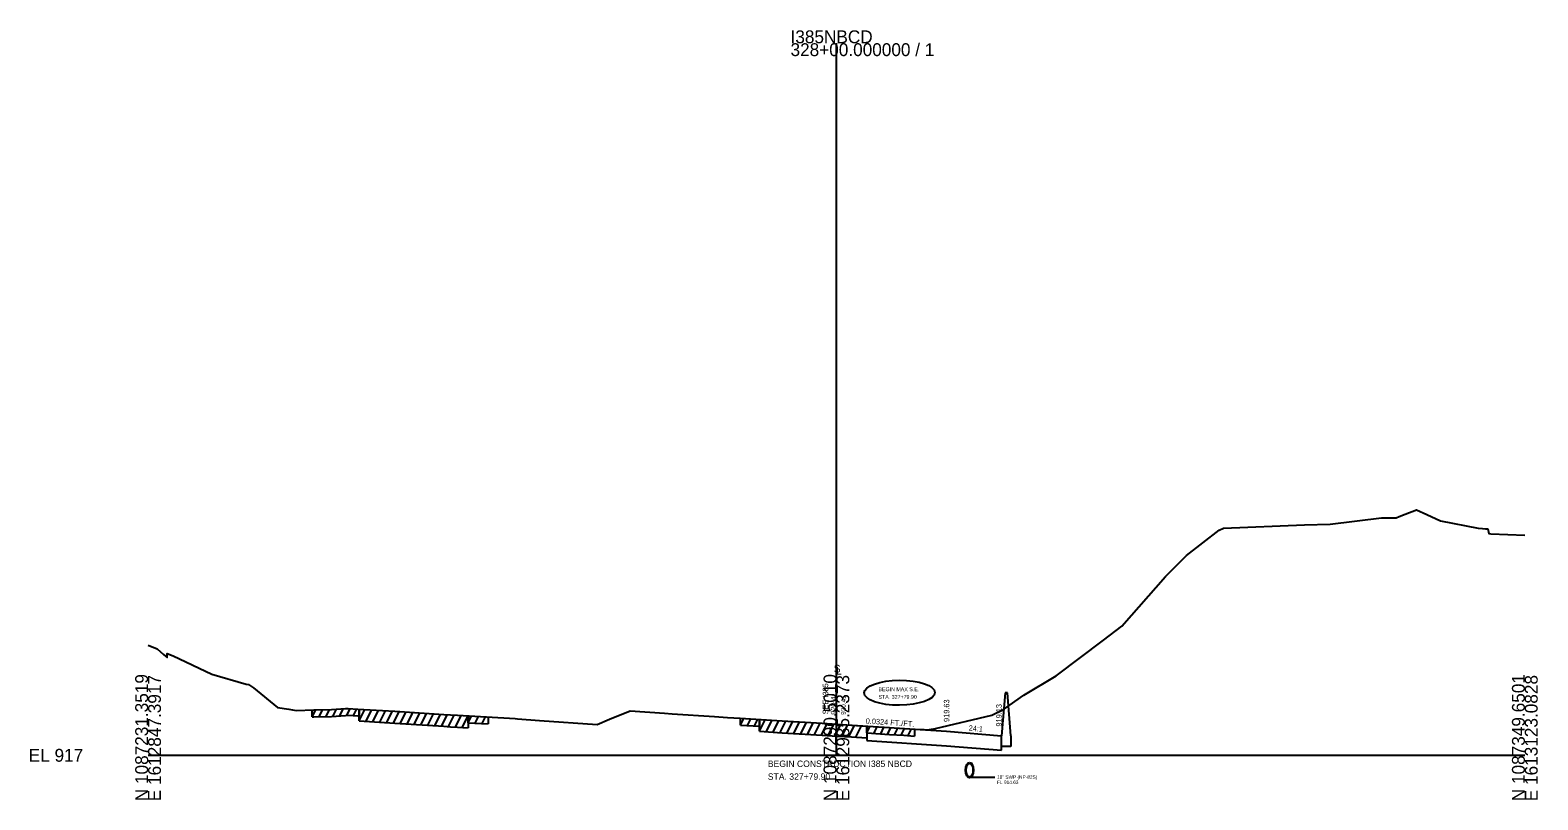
# Model space of a CAD drawing. Extents: x -26 to 1613369, y -10 to 1281970.
# Drawn here: x -25.7 to 302.8, y 490.3 to 657.9 of the extents above; entities that cross this region are included whole.
import ezdxf

# ---------------------------------------------------------------- set-up
doc = ezdxf.new("R2010")
doc.units = 0
for name, color, linetype in [('RD_EX_Misc', 7, 'Continuous'), ('RD_GPK_XS_Cell', 7, 'Continuous'), ('RD_Sketch1', 7, 'Continuous'), ('RD_XS_Base', 7, 'Continuous'), ('RD_XS_ExGround', 7, 'Continuous'), ('RD_XS_ExPaveRet', 7, 'Continuous'), ('RD_XS_MedBbase', 7, 'Continuous'), ('RD_XS_MedBWall', 7, 'Continuous'), ('RD_XS_Pave', 7, 'Continuous'), ('RD_XS_PaveShd', 7, 'Continuous'), ('RD_XS_Pipe', 7, 'Continuous'), ('RD_XS_TX_Elev_EX', 7, 'Continuous'), ('RD_XS_TX_Elev_PR', 7, 'Continuous'), ('RD_XS_TX_MatchLine', 7, 'Continuous'), ('RD_XS_TX_Notes', 7, 'Continuous'), ('RD_XS_TX_ShdSlope', 7, 'Continuous'), ('RD_XS_TX_Slope', 7, 'Continuous')]:
    doc.layers.add(name, color=color, linetype=linetype)

msp = doc.modelspace()

# ---------------------------------------------------------------- linework, layer by layer
at = {"layer": 'RD_EX_Misc'}
for p, q in [((35.78, 508.36), (35.78, 509.86)), ((45.97, 510.07), (45.97, 508.57)), ((35.78, 508.36), (36.1, 508.37)), ((36.1, 508.37), (39.97, 508.46)), ((39.97, 508.46), (43.03, 508.66)), ((43.03, 508.66), (43.63, 508.71)), ((43.63, 508.71), (45.68, 508.58)), ((45.68, 508.58), (45.97, 508.57)), ((69.77, 507.1), (69.77, 508.6)), ((69.77, 507.1), (74.1, 506.85)), ((74.1, 508.35), (74.1, 506.85)), ((129.11, 506.58), (129.11, 508.08)), ((129.11, 506.58), (133.21, 506.32)), ((133.21, 507.82), (133.21, 506.32)), ((156.64, 504.87), (156.64, 506.37)), ((156.64, 504.87), (161.53, 504.54)), ((161.53, 504.54), (164.71, 504.35)), ((164.71, 504.35), (167, 504.19)), ((167, 505.69), (167, 504.19))]:
    msp.add_line(p, q, dxfattribs=at)
at = {"layer": 'RD_GPK_XS_Cell'}
for p, q in [((150, 500), (150, 655.04)), ((0, 500), (150, 500)), ((150, 500), (300, 500))]:
    msp.add_line(p, q, dxfattribs=at)
at = {"layer": 'RD_Sketch1'}
for p, q in [((35.78, 508.36), (36.54, 509.88)), ((37.28, 508.4), (38.04, 509.92)), ((38.78, 508.43), (39.54, 509.95)), ((40.28, 508.48), (41.05, 510.03)), ((41.78, 508.58), (42.55, 510.13)), ((43.28, 508.68), (44.03, 510.19)), ((44.78, 508.64), (45.51, 510.1)), ((69.77, 507.1), (70.5, 508.56)), ((71.27, 507.01), (72, 508.47)), ((72.77, 506.93), (73.5, 508.39)), ((129.11, 506.58), (129.84, 508.03)), ((130.61, 506.49), (131.34, 507.94)), ((132.11, 506.39), (132.84, 507.85)), ((156.64, 504.87), (157.36, 506.32)), ((158.14, 504.77), (158.86, 506.22)), ((159.64, 504.66), (160.36, 506.12)), ((161.14, 504.56), (161.86, 506.02)), ((162.64, 504.47), (163.36, 505.93)), ((164.14, 504.39), (164.86, 505.84)), ((165.64, 504.29), (166.36, 505.74))]:
    msp.add_line(p, q, dxfattribs=at)
at = {"layer": 'RD_XS_Base'}
for p, q in [((150, 506.82), (150.19, 506.8)), ((150.19, 506.8), (153.3, 506.59)), ((153.3, 506.59), (156.64, 506.37)), ((156.64, 506.37), (156.64, 503.22)), ((156.64, 503.22), (174, 502.09)), ((186, 501.09), (186, 504.26)), ((174, 502.09), (186, 501.09))]:
    msp.add_line(p, q, dxfattribs=at)
at = {"layer": 'RD_XS_ExGround'}
msp.add_lwpolyline([(0, 523.98), (2, 523.18), (3.33, 521.94), (4.13, 521.27), (4.13, 522.2), (5.45, 521.67), (13.92, 517.66), (21.41, 515.47), (21.89, 515.41), (23, 514.72), (28.21, 510.42), (30.65, 510.01), (32.24, 509.79), (36.1, 509.87), (39.97, 509.96), (43.03, 510.16), (43.63, 510.21), (45.68, 510.08), (53.76, 509.58), (64.43, 508.91), (65.88, 508.82), (67.42, 508.73), (78.73, 508.09), (79.97, 507.98), (80.52, 507.94), (85.26, 507.59), (97.89, 506.7), (100.52, 507.84), (105.04, 509.66), (112.53, 509.15), (114.21, 509.01), (123.41, 508.44), (126.26, 508.26), (129.04, 508.08), (138.15, 507.51), (146.86, 507), (150.19, 506.8), (153.3, 506.59), (161.53, 506.04), (164.71, 505.85), (167.1, 505.68), (169.13, 505.62), (169.73, 505.57), (171.61, 505.86), (183.85, 508.73), (186.39, 509.99), (190.83, 513.06), (197.85, 517.33), (208.19, 525.09), (212.2, 528.14), (221.71, 538.9), (226.26, 543.48), (233.43, 549.03), (234.32, 549.45), (251.97, 550.19), (257.62, 550.31), (268.76, 551.68), (272, 551.73), (272.64, 551.99), (273.96, 552.51), (276.38, 553.48), (278.66, 552.4), (281.61, 551.06), (289.8, 549.44), (290.81, 549.41), (291.44, 549.3), (291.94, 549.29), (292.19, 548.29), (292.6, 548.22), (300, 547.92)], dxfattribs=at)
at = {"layer": 'RD_XS_ExPaveRet'}
for p, q in [((45.97, 507.47), (45.97, 510.07)), ((45.97, 507.47), (47.23, 509.99)), ((47.47, 507.37), (48.73, 509.9)), ((48.97, 507.28), (50.23, 509.8)), ((50.47, 507.19), (51.73, 509.71)), ((51.97, 507.09), (53.23, 509.62)), ((53.47, 507), (54.73, 509.52)), ((54.97, 506.91), (56.23, 509.43)), ((56.47, 506.81), (57.73, 509.33)), ((57.97, 506.72), (59.23, 509.24)), ((45.97, 507.47), (53.76, 506.98)), ((53.76, 506.98), (64.43, 506.31)), ((59.47, 506.62), (60.73, 509.14)), ((60.97, 506.53), (62.23, 509.05)), ((62.47, 506.43), (63.73, 508.96)), ((63.97, 506.34), (65.23, 508.86)), ((64.43, 506.31), (65.88, 506.22)), ((65.47, 506.25), (66.73, 508.77)), ((65.88, 506.22), (67.42, 506.13)), ((66.97, 506.16), (68.23, 508.68)), ((67.42, 506.13), (69.77, 506)), ((68.47, 506.07), (69.73, 508.6)), ((69.77, 508.6), (69.77, 506)), ((133.21, 505.22), (133.21, 507.82)), ((133.21, 505.22), (134.47, 507.74)), ((134.71, 505.13), (135.97, 507.65)), ((136.21, 505.03), (137.47, 507.55)), ((137.71, 504.94), (138.97, 507.46)), ((139.21, 504.85), (140.47, 507.38)), ((140.71, 504.76), (141.97, 507.29)), ((142.21, 504.68), (143.47, 507.2)), ((143.71, 504.59), (144.97, 507.11)), ((145.21, 504.5), (146.47, 507.03)), ((146.71, 504.41), (147.97, 506.94)), ((148.21, 504.32), (149.47, 506.85)), ((149.71, 504.23), (150.97, 506.75)), ((151.21, 504.13), (152.46, 506.65)), ((152.71, 504.03), (153.96, 506.55)), ((154.21, 503.93), (155.46, 506.45)), ((156.64, 506.37), (156.64, 503.77)), ((133.21, 505.22), (138.15, 504.91)), ((138.15, 504.91), (146.86, 504.4)), ((146.86, 504.4), (150.19, 504.2)), ((150.19, 504.2), (153.3, 503.99)), ((153.3, 503.99), (156.64, 503.77))]:
    msp.add_line(p, q, dxfattribs=at)
at = {"layer": 'RD_XS_MedBbase'}
for p, q in [((186, 501.93), (186, 504.26)), ((188, 504.26), (188, 501.93)), ((188, 501.93), (186, 501.93))]:
    msp.add_line(p, q, dxfattribs=at)
at = {"layer": 'RD_XS_MedBWall'}
for p, q in [((186.75, 513.59), (186, 504.26)), ((187.25, 513.59), (186.75, 513.59)), ((188, 504.26), (187.25, 513.59))]:
    msp.add_line(p, q, dxfattribs=at)
at = {"layer": 'RD_XS_Pave'}
msp.add_line((150, 506.81), (174, 505.26), dxfattribs=at)
at = {"layer": 'RD_XS_PaveShd'}
for p, q in [((150, 506.81), (149.99, 506.82)), ((174, 505.26), (186, 504.26))]:
    msp.add_line(p, q, dxfattribs=at)
at = {"layer": 'RD_XS_Pipe'}
msp.add_line((179.5, 495.26), (184.5, 495.26), dxfattribs=at)
msp.add_line((179.5, 495.26), (184.5, 495.26), dxfattribs=at)
for major_axis in [(0, 1.7), (0, 1.7), (0, 1.5), (0, 1.5)]:
    msp.add_ellipse((179, 496.76), major_axis=major_axis, ratio=0.5, dxfattribs=at)
at = {"layer": 'RD_XS_TX_MatchLine'}
for p, q in [((149.99, 506.82), (149.99, 516.7)), ((149.99, 501.82), (149.99, 506.82))]:
    msp.add_line(p, q, dxfattribs=at)
at = {"layer": 'RD_XS_TX_Notes'}
msp.add_ellipse((163.74, 513.63), major_axis=(7.68, 0.05), ratio=0.355189, dxfattribs=at)

# ---------------------------------------------------------------- texts
at = {"layer": 'RD_GPK_XS_Cell'}
for s, p in [('I385NBCD', (140, 655.04)), ('328+00.000000 / 1', (140, 652.24)), ('EL 917', (-26, 498.6))]:
    msp.add_text(s, height=2.8, dxfattribs=at).set_placement(p)
for s, p in [('N 1087231.3519', (0, 490)), ('E 1612847.3917', (2.8, 490)), ('N 1087290.5010', (150, 490)), ('E 1612985.2373', (152.8, 490)), ('N 1087349.6501', (300, 490)), ('E 1613123.0828', (302.8, 490))]:
    msp.add_text(s, height=2.8, rotation=90, dxfattribs=at).set_placement(p)
at = {"layer": 'RD_XS_Pipe'}
for s, p in [('18" SWP (NP-82S)', (185, 494.88)), ('18" SWP (NP-82S)', (185, 494.88)), ('FL 914.63', (185, 493.76)), ('FL 914.63', (185, 493.76))]:
    msp.add_text(s, height=0.75, dxfattribs=at).set_placement(p)
at = {"layer": 'RD_XS_TX_Elev_EX'}
msp.add_text('920.41', height=1, rotation=90, dxfattribs=at).set_placement((152, 508.82))
at = {"layer": 'RD_XS_TX_Elev_PR'}
for s, p in [('920.41', (149.99, 508.82)), ('919.63', (174.6, 507.26)), ('919.13', (186, 506.26))]:
    msp.add_text(s, height=1.2, rotation=90, dxfattribs=at).set_placement(p)
at = {"layer": 'RD_XS_TX_MatchLine'}
for s, p in [('S', (149.41, 518.02)), ('L', (149.92, 517.58))]:
    msp.add_text(s, height=1.68, dxfattribs=at).set_placement(p)
at = {"layer": 'RD_XS_TX_Notes'}
msp.add_text('SEE I385', height=1.2, rotation=90, dxfattribs=at).set_placement((148.21, 508.91))
for s, height, p in [('STA. 327+79.90', 0.8333, (159.16, 512.3)), ('BEGIN MAX S.E. ', 0.8333, (159.16, 513.96)), ('BEGIN CONSTRUCTION I385 NBCD', 1.4, (135.05, 497.46)), ('STA. 327+79.90', 1.4, (135.05, 494.66))]:
    msp.add_text(s, height=height, dxfattribs=at).set_placement(p)
at = {"layer": 'RD_XS_TX_ShdSlope'}
msp.add_text('24:1', height=1.2, rotation=355.2364, dxfattribs=at).set_placement((178.77, 505.36))
at = {"layer": 'RD_XS_TX_Slope'}
msp.add_text('0.0324 FT./FT.', height=1.2, rotation=356.2924, dxfattribs=at).set_placement((156.35, 506.9))

doc.saveas('drawing.dxf')
